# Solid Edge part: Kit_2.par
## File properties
Author: ahadarics
Last saved by: ahadarics
Revision: 78
Sűrűség: 0,000 kg/m^3
Pontosság: 0,990
Username: ahadarics
Dokumentum tartalom típus: 0
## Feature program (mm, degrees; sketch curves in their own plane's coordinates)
base feature "unnamed BaseFeature 1"
sketch for "Furat_1" plane through (0, 3.75, 13.5) normal (0, 0, 1) x-axis (0, 1, 0)
  hole centre (-0.25, 0) bore radius 4.283
hole "Furat_1" nominal diameter 9.728 finite  ThreadDepth = 7.5 mm
sketch for "Kihúzás_1" #1 plane through (0, 33.5, 0) normal (0, 1, 0) x-axis (0, 0, -1)
  line (-7.5498, 8) -> (7.5498, 8)
sketch for "Kihúzás_1" #2 plane through (0, 33.5, 0) normal (0, 1, 0) x-axis (0, 0, -1)
  arc centre (0, 0) radius 11 from (7.5498, -8) to (-7.5498, -8) cw
  line (7.5498, -8) -> (-7.5498, -8)
extrude "Kihúzás_1" add finite 17.84 along -normal
thread "unnamed Thread 1"
chamfer "Letörés_1" setback 1.5
sketch for "Kivágás_1" #1 plane through (0, 33.5, 0) normal (0, 1, 0) x-axis (0, 0, -1)
  line (7.5498, -8) -> (-7.5498, -8)
  arc centre (0, 0) radius 11 from (7.5498, -8) to (-7.5498, -8) cw
sketch for "Kivágás_1" #2 plane through (0, 33.5, 0) normal (0, 1, 0) x-axis (0, 0, -1)
  line (-7.5498, 8) -> (7.5498, 8)
extrude "Kivágás_1" cut finite 17.84 along -normal
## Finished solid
Body 1: solid body, 57 faces, 117 edges, 67 vertices, 1 internal void.
  Faces by surface: plane 22, cylinder 21, cone 13, spun 1
  Edges by curve: circle 48, line 48, intersection 13, spline 8
Bounding box of the edges (mm; curved faces can reach further): 30.000 x 39.500 x 28.500, from (-15, -6, -15) to (15, 33.5, 13.5).
Cylindrical faces by radius (mm): R0.875 x1, R0.9 x1, R1.7 x1, R1.75 x1, R3 x1, R4 x1, R4.28 x3, R4.283 x1, R6.5 x3, R9.85 x2, R11 x4, R13.5 x1, R15 x1
Conical faces (half-angle, radius in mm at the cone's reference point): 30 deg R1.8366 x1, 45 deg R1.55 x2, 45 deg R4.1 x2, 45 deg R4.28 x1, 45 deg R11 x2, 59 deg R1 x2, 59 deg R2.1415 x1, 60 deg R10.425 x2
Planar faces by outward normal: +x 2, +y 8, +z 6, -x 2, -y 3, -z 1
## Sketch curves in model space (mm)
arc centre (0, 33.5, 0) radius 11 from (-8, 33.5, 7.5498) through (-11, 33.5, 0) to (-8, 33.5, -7.5498)
line (-8, 33.5, 7.5498) -> (-8, 33.5, -7.5498)
arc centre (0, 33.5, 0) radius 11 from (8, 33.5, -7.5498) through (11, 33.5, 0) to (8, 33.5, 7.5498)
line (8, 33.5, -7.5498) -> (8, 33.5, 7.5498)
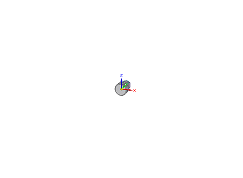
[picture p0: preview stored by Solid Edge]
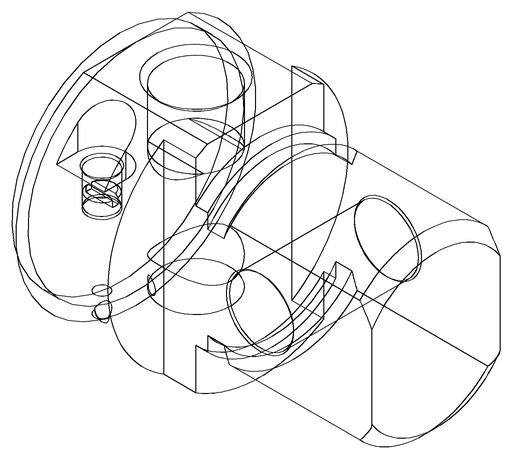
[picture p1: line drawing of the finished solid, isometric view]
